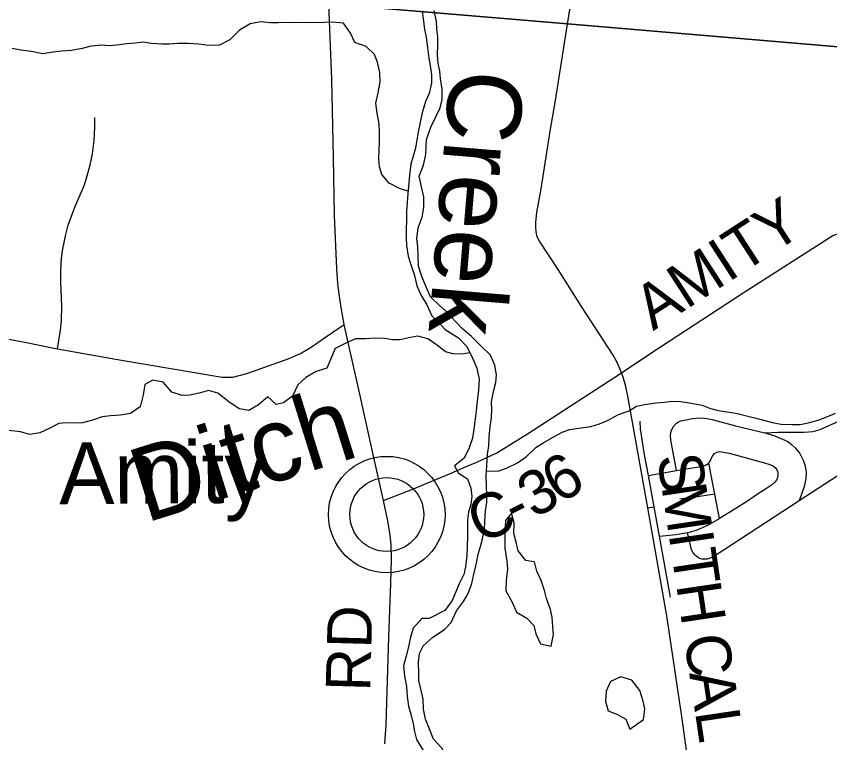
# Model space of a CAD drawing. Extents: x 114843 to 284848, y 317643 to 566895.
# Drawn here: x 133165 to 138651, y 424165 to 429067 of the extents above; entities that cross this region are included whole.
import ezdxf

# ---------------------------------------------------------------- set-up
doc = ezdxf.new("R2010")
doc.units = 0
for name, color, linetype in [('GM_X_County_Road', 7, 'Continuous'), ('GM_X_County_Road_Text', 7, 'Continuous'), ('GM_X_Major_River', 7, 'Continuous'), ('GM_X_Major_River_Text', 7, 'Continuous'), ('GM_X_Minor_Lake', 7, 'Continuous'), ('GM_X_Minor_River', 7, 'Continuous'), ('GM_X_Minor_River_Text', 7, 'Continuous'), ('GM_X_Township', 7, 'Continuous'), ('GM_X_Township_Road', 7, 'Continuous'), ('GM_X_Township_Road_Text', 7, 'Continuous'), ('GM_X_Unincorporated', 7, 'Continuous'), ('GM_X_Unincorporated_Location', 7, 'Continuous'), ('GM_X_Unincorporated_Text', 7, 'Continuous')]:
    doc.layers.add(name, color=color, linetype=linetype)

msp = doc.modelspace()

# ---------------------------------------------------------------- linework, layer by layer
at = {"layer": 'GM_X_County_Road'}
for points in [[(136883.3, 429012.6), (136964.2, 429521.4), (136996.2, 429748.6), (137020.1, 429943.8), (137111.6, 430758), (137127, 430921.1), (137133.7, 431019.1), (137135.8, 431084.7), (137135.8, 431133.3), (137133.5, 431182.9), (137128.2, 431248.2), (137119.5, 431313.1), (136984, 432021), (136923, 432309.6), (136836, 432696.1), (136764.2, 432979.1), (136611.6, 433549), (136529.2, 433866.2), (136493.7, 433990.5), (136458.9, 434084.4), (136432.5, 434144.3), (136335.6, 434329.7)], [(135377, 426987.4), (135355.6, 427102.3), (135342.2, 427192.2), (135334.3, 427264.7), (135326.8, 427362.6), (135312.4, 427722.9), (135305.7, 428116), (135292.9, 428640.1), (135273, 429148.9)], [(129304.5, 428299.3), (129580.4, 428268.6), (129708, 428248.6), (129786.4, 428218.4), (129890.9, 428136.3), (130591.2, 427433.2), (130650.7, 427376.2), (130724.1, 427328.1), (130774.4, 427306.8), (131520.1, 427138.3), (131781.2, 427076.1), (131886.7, 427054), (131967.7, 427040.2), (132071.6, 427026.3), (132546.3, 426966.9), (132758.4, 426942.1), (132946.7, 426915.7), (133026.8, 426902.7), (133233.5, 426865.5), (133387.4, 426833.5), (133444.5, 426823)], [(137246.5, 426660.8), (137458.6, 426803.1), (138066.4, 427201.1), (138670.8, 427586.9), (138763.1, 427615.8), (138829, 427627), (139020.3, 427649.9), (139594.9, 427715.5), (140004, 427757.8), (141086.3, 427849.1), (141231.1, 427861.5), (141256.3, 427865.4), (141611.1, 427895.3)], [(133444.5, 426823), (133874.3, 426745.3), (134554.6, 426630.6), (134624.8, 426632.3), (134721, 426656.9), (134997.9, 426756.3), (135081.2, 426791.1), (135161.5, 426838.7), (135237.3, 426892.6), (135377, 426987.4)], [(135641.7, 425799.7), (135571.6, 426110.6), (135473.8, 426558.4), (135407.8, 426845.6), (135377, 426987.4)], [(135641.7, 425799.7), (135843, 425878.4), (135929.7, 425915.1), (136096.9, 425982.9), (136194.5, 426025.9), (136271.3, 426057.3), (136406.4, 426121.6), (136612, 426249.4), (136733.5, 426327.2), (137246.5, 426660.8)], [(135650.5, 424158.1), (135653.8, 424190.8), (135659.2, 424288.8), (135677.7, 424878.6), (135691.8, 425238.7), (135695.7, 425402.6), (135693.7, 425501), (135686.8, 425566.2), (135671.1, 425663.1), (135641.7, 425799.7)]]:
    msp.add_lwpolyline(points, dxfattribs=at)
at = {"layer": 'GM_X_Major_River'}
for points in [[(135902.2, 429104.1), (135910, 429049.9), (135917.7, 428979.7), (135929.5, 428925.5), (135939.2, 428855.3), (135946.9, 428785.1), (135956.7, 428734.9), (135964.5, 428670.7), (135964.3, 428618.6), (135949.9, 428546.4), (135925.7, 428492.4), (135903.3, 428416.2), (135887, 428342.1), (135874.7, 428288), (135858.2, 428175.7), (135842, 428123.7), (135825.7, 428069.6), (135817.4, 427995.4), (135813.1, 427941.3), (135806.8, 427871.1), (135800.5, 427810.9), (135796.3, 427748.8), (135795.5, 427570.3), (135797.3, 427520.1), (135809, 427447.9), (135822.8, 427397.7), (135850.5, 427317.4), (135866.2, 427247.1), (135894, 427186.8), (135933.8, 427120.5), (135967.5, 427046.2), (136027.3, 426985.8), (136058.1, 426953.6)], [(136058.2, 427081.9), (136019.9, 427116.2), (135958, 427172.6), (135926.3, 427244.9), (135900.6, 427311.2), (135876.8, 427381.5), (135875.1, 427445.6), (135873.4, 427513.8), (135867.6, 427564), (135875.9, 427640.2), (135902.3, 427710.3), (135912.6, 427776.4), (135912.9, 427848.6), (135897.2, 427916.9), (135881.4, 427987.1), (135911.8, 428061.2), (135928.1, 428133.4), (135928.4, 428185.5), (135930.6, 428235.7), (135961, 428317.8), (135993.3, 428383.8), (136023.6, 428449.9), (136037.9, 428506), (136038.2, 428574.2), (136026.5, 428646.4), (136020.7, 428696.6), (136010.9, 428750.8), (136005.1, 428804.9), (136007.4, 428873.1), (136007.6, 428925.3), (136001.9, 428981.4), (135998.1, 429031.6), (135982.3, 429105.8)], [(136055.4, 424930.7), (136099, 424976), (136134.4, 425055.8), (136182.2, 425118.2), (136212.1, 425172.5), (136237.8, 425238.9), (136251.6, 425303.2), (136269.4, 425377.5), (136279.2, 425437.8), (136295, 425488), (136308.8, 425540.3), (136322.6, 425606.5), (136324.4, 425658.7), (136330.2, 425733), (136338, 425783.3), (136337.8, 425839.4), (136335.6, 425893.6), (136333.3, 425967.9), (136339.1, 426032.1), (136342.8, 426112.4), (136352.6, 426168.7), (136354.4, 426226.9), (136362.1, 426299.2), (136369.9, 426357.4), (136371.7, 426411.6), (136369.5, 426465.8), (136383.3, 426534.1), (136399.1, 426596.4), (136402.9, 426646.6), (136392.7, 426712.8), (136362.4, 426780.9), (136300.1, 426840.9), (136235.8, 426906.8), (136171.5, 426960.8), (136058.2, 427081.9)], [(136058.1, 426953.6), (136147.7, 426896.5), (136204, 426838.5), (136244.3, 426756.4), (136270.6, 426692.2), (136286.9, 426618), (136283.2, 426543.8), (136273.4, 426469.5), (136265.7, 426405.2), (136257.9, 426332.9), (136250.1, 426280.7), (136242.3, 426220.4), (136220.5, 426154.1), (136184.7, 426085.7), (136120.8, 426033.3), (136147.1, 425983.2), (136207.3, 425945.3), (136231.5, 425883.2), (136237.7, 425827), (136229.9, 425772.8), (136214.1, 425720.5), (136208.3, 425666.3), (136208.7, 425555.9), (136206.9, 425483.6), (136203.1, 425427.4), (136195.4, 425351.1), (136183.6, 425300.9), (136151.8, 425236.5), (136104.5, 425125), (136054.2, 425057.7)], [(136054.2, 425057.7), (135950.5, 425002.2), (135900.5, 425002.4), (135842.1, 424938.4), (135823.8, 424876.3), (135813.5, 424824.1), (135795.2, 424748), (135776.8, 424683.8), (135782.5, 424615.6), (135796.3, 424545.3), (135802, 424477.1), (135809.7, 424410.9), (135825.5, 424356.7), (135841.2, 424292.4), (135851, 424240.2), (135864.8, 424186), (135908.5, 424113.6), (135956.3, 424043.2), (136012.1, 423990.9), (136054.1, 423980.7)], [(136054.3, 424093), (136034.8, 424129.2), (135979, 424189.6), (135955.2, 424251.9), (135925.5, 424324.2), (135911.8, 424390.4), (135908.1, 424458.7), (135880.6, 424585.2), (135880.8, 424635.3), (135877.1, 424707.6), (135883.4, 424767.7), (135911.7, 424821.8), (135972, 424875.7), (136055.4, 424930.7)]]:
    msp.add_lwpolyline(points, dxfattribs=at)
at = {"layer": 'GM_X_Minor_Lake'}
for points in [[(136504.4, 425713.7), (136464.5, 425665.3), (136462.7, 425615.1), (136459, 425544.9), (136459.2, 425478.6), (136473.5, 425392.4), (136477.7, 425336.2), (136470, 425259.9), (136466.3, 425189.6), (136508.6, 425113.5), (136538.9, 425045.4), (136609.1, 425005.5), (136655.3, 424955.5), (136669.5, 424899.3), (136699.8, 424833.2), (136771.9, 424817.4), (136787.7, 424895.8), (136783.5, 424948), (136779.2, 425012.2), (136767, 425064.3), (136740.7, 425138.5), (136726.5, 425192.6), (136704.3, 425258.8), (136676, 425322.9), (136659.8, 425385.1), (136627, 425390.6)], [(136627, 425390.6), (136601.7, 425394.9), (136549.4, 425458.9), (136539.2, 425509.1), (136520.9, 425577.2), (136522.7, 425649.5), (136504.4, 425713.7)], [(137197.5, 424589.7), (137173.2, 424578.1), (137143.4, 424513.8), (137137.7, 424443.5), (137155.9, 424379.3), (137220.1, 424355.5), (137276.2, 424323.6), (137302.5, 424255.5)], [(137302.5, 424255.5), (137394.4, 424322.1), (137404.1, 424394.4), (137391.9, 424444.5), (137369.6, 424516.7), (137315.3, 424586.7), (137241.2, 424610.5), (137197.5, 424589.7)]]:
    msp.add_lwpolyline(points, dxfattribs=at)
at = {"layer": 'GM_X_Minor_River'}
for points in [[(135808.2, 427886.3), (135748.9, 427905.4), (135678.9, 427939.7), (135631.1, 428000.1), (135615.3, 428050.3), (135609.5, 428104.4), (135611.8, 428162.6), (135614, 428214.7), (135614.3, 428286.9), (135612.5, 428341.1), (135598.8, 428411.3), (135591.1, 428479.5), (135605.4, 428549.7), (135619.7, 428623.8), (135618, 428688), (135600.3, 428756.2), (135580.5, 428808.5), (135524.6, 428862.8), (135448.6, 428889.1), (135418.8, 428953.4), (135371, 429019.8), (135296.9, 429028.1), (135244.8, 429024.2), (135168.7, 429022.5), (135098.6, 429024.7), (135046.5, 429022.9), (134996.4, 429025.1), (134932.3, 429023.3), (134880.2, 429021.5), (134814.2, 429029.8), (134742, 429016), (134671.7, 428972.1), (134605.3, 428908.2), (134535.1, 428872.3), (134460.9, 428868.6), (134394.9, 428878.8), (134326.8, 428883.1), (134252.7, 428883.4), (134198.6, 428877.5), (134148.5, 428877.7), (134074.4, 428882), (134020.3, 428892.2), (133966.2, 428886.4), (133910.1, 428880.6), (133842, 428870.8), (133791.9, 428867), (133741.8, 428871.1), (133669.7, 428865.4), (133609.5, 428849.5), (133537.3, 428835.8), (133467.2, 428832), (133415.1, 428824.2), (133344.9, 428814.4), (133268.9, 428828.7), (133196.8, 428839), (133138.7, 428849.2)], [(136057.9, 426805.2), (136006.7, 426845.5), (135940.8, 426889.8), (135872.8, 426908.1), (135822.7, 426900.3), (135752.5, 426882.5), (135702.4, 426882.7), (135650.4, 426892.9), (135586.3, 426895.1), (135520.1, 426891.3), (135454, 426889.6), (135387.8, 426861.7), (135315.5, 426823.9), (135258.8, 426691.7), (135188.6, 426669.9), (135118.4, 426630), (135064.1, 426580), (135027.7, 426504), (134967.4, 426458), (134917.2, 426446.2), (134861.4, 426498.5), (134799, 426444.6), (134732.8, 426406.7), (134668.7, 426417), (134598.8, 426465.4), (134525, 426523.8), (134460.9, 426542.1), (134398.8, 426524.3), (134336.6, 426510.4), (134284.5, 426508.6), (134214.5, 426530.9), (134156.7, 426597.3), (134086.6, 426611.6), (134032.4, 426581.7), (134022.1, 426511.5), (134001.7, 426431.4), (133935.4, 426385.5), (133867.3, 426375.7), (133801.1, 426369.9), (133745, 426364.1), (133678.8, 426342.3), (133612.6, 426322.4), (133562.5, 426320.6), (133502.5, 426322.8), (133452.4, 426319), (133388.1, 426285.1), (133323.9, 426255.3), (133257.7, 426245.5), (133193.7, 426263.8), (133115.6, 426272.1)], [(136057.9, 426805.2), (136109.6, 426791.9), (136170.6, 426789.4), (136224, 426797.7)], [(136335.9, 425997.3), (136419.3, 426000.4), (136471.3, 426016.6), (136545.2, 426053), (136605.1, 426095.4), (136669, 426155.9), (136722.9, 426190.2), (136796.8, 426232.7), (136846.8, 426261), (136898.8, 426279.3), (136958.8, 426287.5), (137040.9, 426297.9), (137098.9, 426316.2), (137152.9, 426338.5), (137226.8, 426378.9), (137298.8, 426405.3), (137348.7, 426435.6), (137404.7, 426447.8), (137478.8, 426458.2), (137536.8, 426462.4), (137586.8, 426468.6), (137646.9, 426466.9), (137717, 426457.1), (137791.1, 426443.4), (137847.3, 426419.5), (137897.4, 426407.7), (137971.5, 426395.9), (138029.6, 426386.1), (138097.7, 426368.3), (138163.9, 426352.5), (138214, 426338.7), (138274.1, 426322.8), (138324.2, 426315), (138400.3, 426311.3), (138450.3, 426311.5), (138504.4, 426323.7), (138572.4, 426342.1), (138630.3, 426364.4), (138690.3, 426388.7)]]:
    msp.add_lwpolyline(points, dxfattribs=at)
at = {"layer": 'GM_X_Township'}
for points in [[(114843.2, 430764.1), (117843.8, 430522.4), (126052.3, 429791.9), (135271.8, 429151.7), (136882.2, 429015.4), (146565.8, 428193.1), (147386.3, 428151.2), (147381.4, 428076.8), (147234.5, 426587.1), (147185.7, 425924.8), (147068.3, 424330), (146961.8, 422359.1), (146657.9, 418021.9)], [(146565.8, 428193.1), (136882.2, 429015.4), (135271.8, 429151.7), (126052.3, 429791.9), (117843.8, 430522.4), (114843.2, 430764.1)]]:
    msp.add_lwpolyline(points, dxfattribs=at)
at = {"layer": 'GM_X_Township_Road'}
for p, q in [((137876.6, 425841.5), (137835.8, 426051.7)), ((137429.4, 425968.6), (137617, 426001.9)), ((137467.3, 425755.7), (137429.4, 425968.6)), ((137906.7, 425677), (137876.6, 425841.5)), ((137424.5, 425749), (137467.3, 425755.7)), ((137502.5, 425558.5), (137467.3, 425755.7)), ((137575.9, 425146.2), (137502.5, 425558.5))]:
    msp.add_line(p, q, dxfattribs=at)
for points in [[(137246.5, 426660.8), (137221.9, 426722.3), (137189.5, 426779.3), (136976.1, 427109.2), (136818.7, 427358.3), (136693.1, 427550), (136678.9, 427579.5), (136671.3, 427611.4), (136668.4, 427644), (136668.6, 427676.7), (136676.6, 427741.8), (136704.3, 427903.3), (136766.2, 428291.7), (136799.1, 428485.7), (136883.3, 429012.6)], [(133444.5, 426823), (133464.6, 426949.8), (133470.9, 427013.9), (133472.7, 427110.7), (133467, 427272.2), (133465.8, 427349.5), (133471.5, 427434.1), (133479.8, 427498.1), (133498.8, 427594.1), (133515.9, 427656.9), (133536.9, 427718.4), (133560.5, 427779), (133624.8, 427928.9), (133644.3, 427989.1), (133664.3, 428063.8), (133678.7, 428138), (133690.4, 428229.1), (133695.6, 428321), (133696.1, 428382.8)], [(137424.5, 425749), (137290, 426504.1), (137275.8, 426567.9), (137257.1, 426630.8), (137246.5, 426660.8)], [(138212.6, 426257), (138301, 426259.4), (138478.2, 426260.4), (138538.1, 426265.7), (138587, 426278.8), (138841.6, 426392.6), (138873.9, 426399.7), (138896.5, 426398.9), (139008.6, 426383), (139032.2, 426375.3), (139052.9, 426366.6), (139082.5, 426338.4), (139100.9, 426307.5), (139105, 426291.9), (139104.6, 426275.1), (139100.9, 426258.1), (139094.6, 426242.1), (139086.5, 426227.9), (139067.2, 426202.6), (139055.7, 426191.4), (138876.7, 426075.9), (138862.6, 426069), (138836, 426050.3), (138444.2, 425796.6)], [(137429.4, 425968.6), (137402.3, 426108.5), (137375.4, 426282.1), (137372.2, 426335.2)], [(137617, 426001.9), (137602.6, 426087.8), (137580, 426206.2), (137576.7, 426241.7), (137580.6, 426266.8), (137595, 426296.3), (137617.6, 426320.1), (137631, 426329.5), (137645.7, 426336.6), (137726.2, 426353), (137775.6, 426357), (137808.5, 426355.7), (137857, 426346.9), (138015.5, 426304.3), (138212.6, 426257)], [(138212.6, 426257), (138279.9, 426235.9), (138367.1, 426197.6), (138394, 426178.2), (138418, 426155.2), (138448.3, 426115.5), (138470.7, 426070.5), (138485.6, 426032.2), (138492.1, 425987.4), (138489.3, 425945.8), (138477.3, 425892.9), (138444.2, 425796.6)], [(137835.8, 426051.7), (137846.4, 426069.2), (137858.6, 426097.1), (137873.9, 426115.7), (137889.2, 426126.6), (137909.3, 426129.9), (137973.2, 426119.2), (138211.5, 426054.6), (138247.2, 426042.9), (138271, 426031.2), (138285.1, 426019.5), (138294.9, 426006.8), (138300.1, 425991.2), (138301.5, 425973.4), (138299.1, 425953.5), (138292, 425936.1), (138280.3, 425922), (138257.1, 425902.4), (138217.5, 425875.4), (138162.6, 425841.4), (138095.6, 425793.9), (138018.5, 425744.9), (137906.7, 425677)], [(137617, 426001.9), (137683.3, 426014.1), (137782.4, 426029), (137809.6, 426036.5), (137835.8, 426051.7)], [(137876.6, 425841.5), (137758.7, 425823.2), (137640, 425808.5)], [(138444.2, 425796.6), (137939.4, 425466.1), (137868.3, 425422.3), (137838.8, 425408.3), (137823.6, 425404.3), (137807.8, 425402.6), (137791.5, 425403.9), (137775.5, 425408.5), (137760.4, 425415.8), (137746.9, 425425), (137735.6, 425436.9), (137726.5, 425450.9), (137719.7, 425466.3), (137692.5, 425583.7)], [(137697.9, 424017.5), (137653.4, 424341.7), (137552.1, 425021.2), (137424.5, 425749)], [(137692.5, 425583.7), (137714, 425588), (137757.2, 425601), (137833.2, 425634.1), (137906.7, 425677)], [(137502.5, 425558.5), (137612.4, 425570.7), (137666.1, 425578.3), (137692.5, 425583.7)]]:
    msp.add_lwpolyline(points, dxfattribs=at)
at = {"layer": 'GM_X_Unincorporated'}
for radius in [392.9, 249]:
    msp.add_circle((135663.6, 425704.5), radius, dxfattribs=at)
at = {"layer": 'GM_X_Unincorporated_Location'}
msp.add_line((135663.6, 425704.5), (135663.6, 425704.5), dxfattribs=at)

# ---------------------------------------------------------------- texts
at = {"layer": 'GM_X_County_Road_Text'}
for s, height, rotation, p in [('AMITY', 300.01, 32.8839, (137459.7, 426941.7)), ('6', 300, 31.7397, (136829.3, 425771.5)), ('3', 300, 29.3873, (136656.6, 425674)), ('C', 300, 23.9048, (136293.5, 425504.4)), ('-', 300, 26.874, (136534.1, 425611.5)), ('RD', 300.01, 88.4377, (135551.5, 424508.6))]:
    msp.add_text(s, height=height, rotation=rotation, dxfattribs=at).set_placement(p)
at = {"layer": 'GM_X_Major_River_Text'}
msp.add_text('Creek', height=500.14, rotation=265.2353, dxfattribs=at).set_placement((136093.5, 428719.2))
at = {"layer": 'GM_X_Minor_River_Text'}
msp.add_text('Ditch', height=500.07, rotation=17.3641, dxfattribs=at).set_placement((134035.2, 425646.3))
at = {"layer": 'GM_X_Township_Road_Text'}
for s, rotation, p in [('S', 278.4342, (137486, 426097.5)), ('M', 278.4324, (137515.7, 425897.3)), ('I', 278.435, (137563.4, 425575.2)), ('T', 278.4344, (137581.5, 425453.3)), ('H', 278.4327, (137614.4, 425231.3)), ('C', 278.4339, (137666.7, 424878.7)), ('A', 278.4335, (137702.8, 424635)), ('L', 278.4335, (137741.6, 424373.9))]:
    msp.add_text(s, height=300, rotation=rotation, dxfattribs=at).set_placement(p)
at = {"layer": 'GM_X_Unincorporated_Text'}
msp.add_text('Amity', height=417.01, rotation=0.4114, dxfattribs=at).set_placement((133455.8, 425774.1))

doc.saveas('drawing.dxf')
